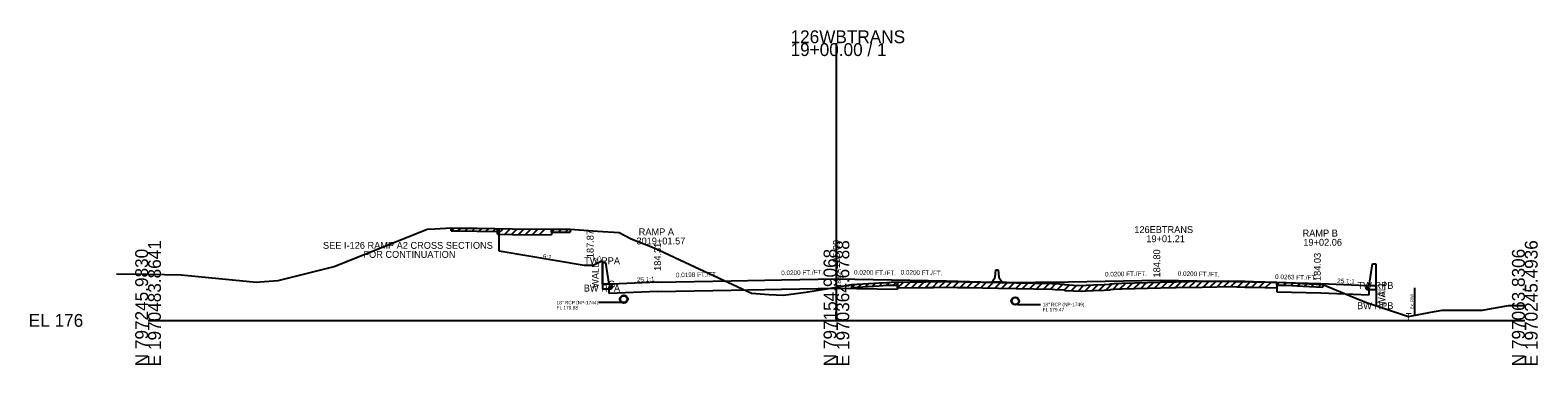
# Model space of a CAD drawing. Extents: x -6494 to 1970605, y -10 to 798140.
# Drawn here: x 974.3 to 1302.8, y 1490.3 to 1563.3 of the extents above; entities that cross this region are included whole.
import ezdxf

# ---------------------------------------------------------------- set-up
doc = ezdxf.new("R2010")
doc.units = 0
for name, color, linetype in [('Default', 7, 'Continuous'), ('RD_EX_SU_Misc_TxCode', 7, 'Continuous'), ('RD_GPK_XS_Cell', 7, 'Continuous'), ('RD_Sketch1', 7, 'Continuous'), ('RD_XS_Base', 7, 'Continuous'), ('RD_XS_Box', 7, 'Continuous'), ('RD_XS_EwShp', 7, 'Continuous'), ('RD_XS_ExGround', 7, 'Continuous'), ('RD_XS_ExPaveRet', 7, 'Continuous'), ('RD_XS_ExRW', 7, 'Continuous'), ('RD_XS_MedBWall', 7, 'Continuous'), ('RD_XS_Misc_Line', 7, 'Continuous'), ('RD_XS_Pave', 7, 'Continuous'), ('RD_XS_PaveOvlay', 7, 'Continuous'), ('RD_XS_PaveShd', 7, 'Continuous'), ('RD_XS_Pipe', 7, 'Continuous'), ('RD_XS_TieSlope', 7, 'Continuous'), ('RD_XS_TX_Elev_EX', 7, 'Continuous'), ('RD_XS_TX_Elev_PR', 7, 'Continuous'), ('RD_XS_TX_Misc', 7, 'Continuous'), ('RD_XS_TX_Notes', 7, 'Continuous'), ('RD_XS_TX_Profile', 7, 'Continuous'), ('RD_XS_TX_Slope', 7, 'Continuous'), ('RD_XS_TX_Station', 7, 'Continuous')]:
    doc.layers.add(name, color=color, linetype=linetype)

msp = doc.modelspace()

# ---------------------------------------------------------------- linework, layer by layer
at = {"layer": 'Default'}
for p, q in [((1184, 1508.57), (1184.58, 1509.41)), ((1184, 1508.32), (1184, 1508.57)), ((1186, 1508.32), (1184, 1508.32)), ((1184.58, 1509.41), (1184.75, 1510.99)), ((1184.75, 1510.99), (1185.25, 1510.99)), ((1185.25, 1510.99), (1185.42, 1509.41)), ((1185.42, 1509.41), (1186, 1508.57)), ((1186, 1508.57), (1186, 1508.32))]:
    msp.add_line(p, q, dxfattribs=at)
at = {"layer": 'RD_GPK_XS_Cell'}
for p, q in [((1150, 1500), (1150, 1560.44)), ((1000, 1500), (1150, 1500)), ((1150, 1500), (1300, 1500))]:
    msp.add_line(p, q, dxfattribs=at)
at = {"layer": 'RD_XS_Base'}
for p, q in [((1100.51, 1507.33), (1101.01, 1507.35)), ((1100.51, 1505.85), (1100.51, 1507.33)), ((1111.03, 1506.27), (1100.51, 1505.85)), ((1101.01, 1507.35), (1101.01, 1507.91)), ((1111.03, 1506.27), (1127.07, 1506.59)), ((1127.07, 1506.59), (1138, 1506.81)), ((1138, 1506.81), (1150, 1507.05)), ((1150, 1507.05), (1163.33, 1506.79)), ((1245.97, 1506.23), (1255.54, 1505.99)), ((1255.54, 1505.99), (1266.08, 1505.57)), ((1265.57, 1507.07), (1265.57, 1507.63)), ((1266.08, 1507.05), (1265.57, 1507.07)), ((1266.08, 1505.57), (1266.08, 1507.05))]:
    msp.add_line(p, q, dxfattribs=at)
at = {"layer": 'RD_XS_Box'}
for p, q in [((1099.01, 1507.91), (1099.01, 1513)), ((1101.01, 1507.91), (1099.01, 1507.91)), ((1265.57, 1507.63), (1267.58, 1507.63)), ((1267.58, 1507.63), (1267.58, 1503.2))]:
    msp.add_line(p, q, dxfattribs=at)
at = {"layer": 'RD_XS_ExGround'}
msp.add_line((993.14, 1510.18), (1000, 1510.06), dxfattribs=at)
msp.add_lwpolyline([(1000, 1510.06), (1007.24, 1509.94), (1023.66, 1508.34), (1024.35, 1508.39), (1028.35, 1508.71), (1040.54, 1511.76), (1060.83, 1519.88), (1062.47, 1519.98), (1066.06, 1520.15), (1067.38, 1520.13), (1071.68, 1520.09), (1079.4, 1519.97), (1088.65, 1519.87), (1090.68, 1519.87), (1091.95, 1519.86), (1097.92, 1519.45), (1102.65, 1519.13), (1105.27, 1517.78), (1110.26, 1515.85), (1119.17, 1511.67), (1131.47, 1505.95), (1135.25, 1505.67), (1138.44, 1505.47), (1142.27, 1506), (1143.81, 1506.26), (1150, 1507.27), (1153.33, 1507.82), (1159.29, 1508.19), (1160.96, 1508.3), (1161.92, 1508.31), (1169.5, 1508.43), (1171.12, 1508.46), (1173.49, 1508.51), (1176.35, 1508.45), (1178.24, 1508.42), (1185.34, 1508.3), (1196.94, 1508.05), (1197.69, 1508.02), (1199.55, 1507.92), (1199.77, 1507.8), (1201.65, 1507.7), (1203.34, 1507.62), (1204.4, 1507.68), (1206.01, 1507.78), (1208.31, 1507.85), (1209.51, 1507.89), (1209.71, 1507.99), (1210.53, 1508.03), (1212.17, 1508.12), (1220.62, 1508.34), (1223.58, 1508.41), (1224.01, 1508.42), (1229.68, 1508.53), (1232.89, 1508.59), (1235.52, 1508.62), (1239, 1508.53), (1239.95, 1508.5), (1240.86, 1508.47), (1248.02, 1508.27), (1251.62, 1508.08), (1255.97, 1507.85), (1264.04, 1504.52), (1265.7, 1503.84), (1266.58, 1503.54), (1274.63, 1500.84), (1279.53, 1501.79), (1281.98, 1502.24), (1287.01, 1502.25), (1290.76, 1502.24), (1291.15, 1502.32), (1296.43, 1503.22), (1298.92, 1503.22), (1300, 1503.22)], dxfattribs=at)
at = {"layer": 'RD_XS_ExPaveRet'}
for p, q in [((1066.06, 1519.52), (1066.06, 1520.15)), ((1066.06, 1519.52), (1067.38, 1519.5)), ((1067.38, 1519.5), (1071.68, 1519.46)), ((1071.68, 1519.46), (1076.15, 1519.4)), ((1076.15, 1518.77), (1076.15, 1520.02)), ((1076.15, 1520.02), (1076.15, 1519.4)), ((1076.15, 1518.77), (1079.4, 1518.72)), ((1079.4, 1518.72), (1087.92, 1518.63)), ((1087.92, 1519.88), (1087.92, 1518.63)), ((1087.92, 1519.25), (1087.92, 1519.88)), ((1087.92, 1519.25), (1088.65, 1519.24)), ((1088.65, 1519.24), (1090.68, 1519.24)), ((1090.68, 1519.24), (1091.95, 1519.24)), ((1091.95, 1519.86), (1091.95, 1519.24)), ((1163.33, 1507.08), (1163.33, 1508.33)), ((1163.33, 1508.33), (1163.33, 1507.71)), ((1245.97, 1508.33), (1245.97, 1507.08)), ((1245.97, 1507.71), (1245.97, 1508.33)), ((1153.33, 1507.19), (1153.33, 1507.82)), ((1153.33, 1507.19), (1159.29, 1507.57)), ((1159.29, 1507.57), (1160.96, 1507.67)), ((1160.96, 1507.67), (1161.92, 1507.68)), ((1161.92, 1507.68), (1163.33, 1507.71)), ((1163.33, 1507.08), (1169.5, 1507.18)), ((1169.5, 1507.18), (1171.12, 1507.21)), ((1171.12, 1507.21), (1173.49, 1507.26)), ((1173.49, 1507.26), (1176.35, 1507.2)), ((1176.35, 1507.2), (1178.24, 1507.17)), ((1178.24, 1507.17), (1185.34, 1507.05)), ((1185.34, 1507.05), (1196.94, 1506.8)), ((1196.94, 1506.8), (1197.69, 1506.77)), ((1197.69, 1506.77), (1199.55, 1506.67)), ((1199.55, 1506.67), (1199.77, 1506.55)), ((1199.77, 1506.55), (1201.65, 1506.45)), ((1201.65, 1506.45), (1203.34, 1506.37)), ((1203.34, 1506.37), (1204.4, 1506.43)), ((1204.4, 1506.43), (1206.01, 1506.53)), ((1206.01, 1506.53), (1208.31, 1506.6)), ((1208.31, 1506.6), (1209.51, 1506.64)), ((1209.51, 1506.64), (1209.71, 1506.74)), ((1209.71, 1506.74), (1210.53, 1506.78)), ((1210.53, 1506.78), (1212.17, 1506.87)), ((1212.17, 1506.87), (1220.62, 1507.09)), ((1220.62, 1507.09), (1223.58, 1507.16)), ((1223.58, 1507.16), (1224.01, 1507.17)), ((1224.01, 1507.17), (1229.68, 1507.28)), ((1229.68, 1507.28), (1232.89, 1507.34)), ((1232.89, 1507.34), (1235.52, 1507.37)), ((1235.52, 1507.37), (1239, 1507.28)), ((1239, 1507.28), (1239.95, 1507.25)), ((1239.95, 1507.25), (1240.86, 1507.22)), ((1240.86, 1507.22), (1245.97, 1507.08)), ((1245.97, 1507.71), (1248.02, 1507.65)), ((1248.02, 1507.65), (1251.62, 1507.46)), ((1251.62, 1507.46), (1255.97, 1507.23)), ((1255.97, 1507.85), (1255.97, 1507.23))]:
    msp.add_line(p, q, dxfattribs=at)
at = {"layer": 'RD_XS_ExRW'}
msp.add_line((1275.98, 1507.1), (1275.98, 1501.1), dxfattribs=at)
at = {"layer": 'RD_XS_MedBWall'}
for p, q in [((1099.76, 1512.58), (1099.01, 1512.58)), ((1099.01, 1512.58), (1099.01, 1506.91)), ((1100.51, 1507.91), (1099.76, 1512.58)), ((1266.07, 1507.63), (1266.82, 1512.3)), ((1266.82, 1512.3), (1267.57, 1512.3)), ((1267.57, 1512.3), (1267.57, 1506.63)), ((1099.01, 1506.91), (1101.01, 1506.91)), ((1101.01, 1507.91), (1100.51, 1507.91)), ((1101.01, 1506.91), (1101.01, 1507.91)), ((1265.57, 1506.63), (1265.57, 1507.63)), ((1265.57, 1507.63), (1266.07, 1507.63)), ((1267.57, 1506.63), (1265.57, 1506.63))]:
    msp.add_line(p, q, dxfattribs=at)
at = {"layer": 'RD_XS_Misc_Line'}
for p, q in [((1066.06, 1519.52), (1066.68, 1520.14)), ((1067.57, 1519.5), (1068.2, 1520.12)), ((1069.09, 1519.49), (1069.71, 1520.11)), ((1070.6, 1519.47), (1071.22, 1520.09)), ((1072.11, 1519.45), (1072.73, 1520.07)), ((1073.63, 1519.43), (1074.25, 1520.05)), ((1075.14, 1519.41), (1075.76, 1520.03)), ((1076.15, 1518.77), (1077.39, 1520)), ((1077.66, 1518.75), (1078.9, 1519.98)), ((1079.17, 1518.73), (1080.42, 1519.96)), ((1080.69, 1518.71), (1081.93, 1519.95)), ((1082.2, 1518.69), (1083.45, 1519.93)), ((1083.71, 1518.67), (1084.96, 1519.91)), ((1085.23, 1518.66), (1086.47, 1519.89)), ((1087.92, 1519.25), (1088.54, 1519.87)), ((1089.43, 1519.24), (1090.06, 1519.87)), ((1090.94, 1519.24), (1091.57, 1519.86)), ((1156.36, 1507.38), (1157.03, 1508.05)), ((1157.87, 1507.48), (1158.54, 1508.14)), ((1159.38, 1507.57), (1160.06, 1508.24)), ((1160.9, 1507.67), (1161.54, 1508.3)), ((1162.41, 1507.69), (1163.05, 1508.33)), ((1163.33, 1507.08), (1164.61, 1508.35)), ((1164.84, 1507.11), (1166.13, 1508.38)), ((1166.36, 1507.13), (1167.64, 1508.4)), ((1167.87, 1507.16), (1169.15, 1508.43)), ((1169.38, 1507.18), (1170.67, 1508.46)), ((1170.9, 1507.21), (1172.18, 1508.48)), ((1172.41, 1507.24), (1173.69, 1508.5)), ((1173.92, 1507.25), (1175.16, 1508.48)), ((1175.44, 1507.22), (1176.68, 1508.45)), ((1176.95, 1507.19), (1178.19, 1508.42)), ((1178.46, 1507.17), (1179.7, 1508.4)), ((1179.98, 1507.14), (1181.22, 1508.37)), ((1181.49, 1507.12), (1182.73, 1508.35)), ((1183, 1507.09), (1184.24, 1508.32)), ((1184.52, 1507.06), (1185.75, 1508.29)), ((1186.03, 1507.04), (1187.26, 1508.26)), ((1187.54, 1507), (1188.78, 1508.23)), ((1189.06, 1506.97), (1190.29, 1508.19)), ((1190.57, 1506.94), (1191.8, 1508.16)), ((1192.08, 1506.91), (1193.32, 1508.13)), ((1193.6, 1506.87), (1194.83, 1508.1)), ((1195.11, 1506.84), (1196.34, 1508.07)), ((1196.62, 1506.81), (1197.83, 1508.01)), ((1208.73, 1506.62), (1210.14, 1508.01)), ((1210.24, 1506.77), (1211.57, 1508.09)), ((1211.76, 1506.85), (1213.06, 1508.14)), ((1213.27, 1506.9), (1214.56, 1508.18)), ((1214.78, 1506.94), (1216.08, 1508.22)), ((1216.3, 1506.98), (1217.59, 1508.26)), ((1217.81, 1507.02), (1219.1, 1508.3)), ((1219.32, 1507.05), (1220.62, 1508.34)), ((1220.83, 1507.09), (1222.13, 1508.38)), ((1222.35, 1507.13), (1223.64, 1508.42)), ((1223.86, 1507.17), (1225.15, 1508.44)), ((1225.37, 1507.2), (1226.66, 1508.47)), ((1226.89, 1507.23), (1228.17, 1508.5)), ((1228.4, 1507.25), (1229.69, 1508.53)), ((1229.91, 1507.28), (1231.2, 1508.56)), ((1231.43, 1507.31), (1232.71, 1508.58)), ((1232.94, 1507.34), (1234.22, 1508.6)), ((1234.45, 1507.36), (1235.72, 1508.62)), ((1235.97, 1507.36), (1237.19, 1508.58)), ((1237.48, 1507.32), (1238.71, 1508.53)), ((1238.99, 1507.28), (1240.22, 1508.49)), ((1240.51, 1507.23), (1241.73, 1508.45)), ((1242.02, 1507.19), (1243.25, 1508.41)), ((1243.53, 1507.15), (1244.76, 1508.36)), ((1245.97, 1507.71), (1246.58, 1508.31)), ((1247.48, 1507.66), (1248.09, 1508.27)), ((1248.99, 1507.6), (1249.59, 1508.19)), ((1250.51, 1507.52), (1251.1, 1508.11)), ((1252.02, 1507.44), (1252.62, 1508.03)), ((1153.33, 1507.19), (1154, 1507.86)), ((1154.84, 1507.29), (1155.52, 1507.95)), ((1198.14, 1506.74), (1199.33, 1507.93)), ((1199.65, 1506.62), (1200.79, 1507.75)), ((1201.16, 1506.48), (1202.36, 1507.66)), ((1202.68, 1506.4), (1203.94, 1507.65)), ((1204.19, 1506.42), (1205.53, 1507.75)), ((1205.7, 1506.51), (1207.02, 1507.81)), ((1207.22, 1506.57), (1208.52, 1507.86)), ((1253.53, 1507.36), (1254.13, 1507.95)), ((1255.05, 1507.27), (1255.64, 1507.87))]:
    msp.add_line(p, q, dxfattribs=at)
at = {"layer": 'RD_XS_Pave'}
for p, q in [((1111.03, 1508.31), (1127.07, 1508.63)), ((1138, 1508.85), (1150, 1509.09)), ((1150, 1509.09), (1174, 1508.61)), ((1196.55, 1508.32), (1220.55, 1508.8)), ((1220.55, 1508.8), (1232.55, 1508.56)), ((1232.55, 1508.56), (1244.55, 1508.32)), ((1244.55, 1508.32), (1255.54, 1508.03))]:
    msp.add_line(p, q, dxfattribs=at)
at = {"layer": 'RD_XS_PaveOvlay'}
for p, q in [((1163.33, 1508.33), (1169.5, 1508.43)), ((1163.33, 1508.33), (1163.33, 1506.79)), ((1169.5, 1508.43), (1171.12, 1508.46)), ((1171.12, 1508.46), (1173.49, 1508.51)), ((1173.49, 1508.51), (1176.35, 1508.45)), ((1176.35, 1508.45), (1178.24, 1508.42)), ((1178.24, 1508.42), (1185.34, 1508.3)), ((1185.34, 1508.3), (1196.94, 1508.05)), ((1196.94, 1508.05), (1197.69, 1508.02)), ((1197.69, 1508.02), (1199.55, 1507.92)), ((1209.51, 1507.89), (1209.71, 1507.99)), ((1209.71, 1507.99), (1210.53, 1508.03)), ((1210.53, 1508.03), (1212.17, 1508.12)), ((1212.17, 1508.12), (1220.62, 1508.34)), ((1220.62, 1508.34), (1223.58, 1508.41)), ((1223.58, 1508.41), (1224.01, 1508.42)), ((1224.01, 1508.42), (1229.68, 1508.53)), ((1229.68, 1508.53), (1232.89, 1508.59)), ((1232.89, 1508.59), (1235.52, 1508.62)), ((1235.52, 1508.62), (1239, 1508.53)), ((1239, 1508.53), (1239.95, 1508.5)), ((1239.95, 1508.5), (1240.86, 1508.47)), ((1240.86, 1508.47), (1245.97, 1508.33)), ((1245.97, 1508.33), (1245.97, 1506.23)), ((1199.55, 1507.92), (1199.77, 1507.8)), ((1199.77, 1507.8), (1201.65, 1507.7)), ((1201.65, 1507.7), (1203.34, 1507.62)), ((1203.34, 1507.62), (1204.4, 1507.68)), ((1204.4, 1507.68), (1206.01, 1507.78)), ((1206.01, 1507.78), (1208.31, 1507.85)), ((1208.31, 1507.85), (1209.51, 1507.89))]:
    msp.add_line(p, q, dxfattribs=at)
at = {"layer": 'RD_XS_PaveShd'}
for p, q in [((1111.03, 1508.31), (1101.01, 1507.91)), ((1127.07, 1508.63), (1138, 1508.85)), ((1174, 1508.61), (1184, 1508.32)), ((1190.21, 1508.2), (1184, 1508.32)), ((1196.55, 1508.32), (1190.21, 1508.2)), ((1255.54, 1508.03), (1265.57, 1507.63))]:
    msp.add_line(p, q, dxfattribs=at)
at = {"layer": 'RD_XS_Pipe'}
for p, q in [((1103.16, 1503.88), (1098.16, 1503.88)), ((1189.46, 1503.47), (1194.46, 1503.47))]:
    msp.add_line(p, q, dxfattribs=at)
for centre, radius in [((1103.66, 1504.63), 0.85), ((1103.66, 1504.63), 0.75), ((1188.96, 1504.22), 0.85), ((1188.96, 1504.22), 0.75)]:
    msp.add_circle(centre, radius, dxfattribs=at)
at = {"layer": 'RD_XS_TieSlope'}
for p, q in [((1076.52, 1515.08), (1076.52, 1520.02)), ((1095.01, 1512), (1076.52, 1515.08)), ((1097.01, 1512), (1095.01, 1512)), ((1099.01, 1513), (1097.01, 1512))]:
    msp.add_line(p, q, dxfattribs=at)

# ---------------------------------------------------------------- texts
at = {"layer": 'RD_EX_SU_Misc_TxCode'}
msp.add_text('G', height=1.5, dxfattribs=at).set_placement((1100.26, 1507.16))
at = {"layer": 'RD_GPK_XS_Cell'}
for s, p in [('126WBTRANS', (1140, 1560.44)), ('19+00.00 / 1', (1140, 1557.64)), ('EL 176', (974, 1498.6))]:
    msp.add_text(s, height=2.8, dxfattribs=at).set_placement(p)
for s, p in [('N 797245.9830', (1000, 1490)), ('E 1970483.8641', (1002.8, 1490)), ('N 797154.9068', (1150, 1490)), ('E 1970364.6788', (1152.8, 1490)), ('N 797063.8306', (1300, 1490)), ('E 1970245.4936', (1302.8, 1490))]:
    msp.add_text(s, height=2.8, rotation=90, dxfattribs=at).set_placement(p)
at = {"layer": 'RD_Sketch1'}
msp.add_text('T', height=1.5, dxfattribs=at).set_placement((1274.08, 1500.09))
at = {"layer": 'RD_XS_EwShp'}
for s, p in [('TW RPA', (1095.04, 1512.25)), ('TW RPB', (1263.56, 1506.88)), ('BW RPA', (1094.94, 1506.29)), ('BW RPB', (1263.45, 1502.45))]:
    msp.add_text(s, height=1.5, dxfattribs=at).set_placement(p)
at = {"layer": 'RD_XS_ExRW'}
msp.add_text('Ex. R/W ', height=0.65, rotation=90, dxfattribs=at).set_placement((1275.73, 1502.48))
at = {"layer": 'RD_XS_Pipe'}
for s, p in [('18" RCP (NP-1744)', (1089.01, 1503.51)), ('FL 179.88', (1089.01, 1502.38)), ('18" RCP (NP-1749)', (1194.96, 1503.09)), ('FL 179.47', (1194.96, 1501.97))]:
    msp.add_text(s, height=0.75, dxfattribs=at).set_placement(p)
at = {"layer": 'RD_XS_TX_Elev_EX'}
msp.add_text('183.27', height=1, rotation=90, dxfattribs=at).set_placement((1151, 1507.27))
at = {"layer": 'RD_XS_TX_Elev_PR'}
for s, p in [('184.31', (1111.78, 1510.79)), ('185.09', (1150.75, 1511.42)), (' 184.80', (1220.55, 1508.8)), (' 184.03', (1255.54, 1508.03))]:
    msp.add_text(s, height=1.5, rotation=90, dxfattribs=at).set_placement(p)
at = {"layer": 'RD_XS_TX_Misc'}
msp.add_text('187.87', height=1.5, rotation=90, dxfattribs=at).set_placement((1097.09, 1513.57))
at = {"layer": 'RD_XS_TX_Notes'}
for s, p in [('SEE I-126 RAMP A2 CROSS SECTIONS', (1038.12, 1515.61)), ('FOR CONTINUATION', (1046.93, 1513.64))]:
    msp.add_text(s, height=1.5, dxfattribs=at).set_placement(p)
for p in [(1098.2, 1507.1), (1269.58, 1503.15)]:
    msp.add_text('WALL', height=1.5, rotation=90, dxfattribs=at).set_placement(p)
at = {"layer": 'RD_XS_TX_Profile'}
msp.add_text('25.1:1', height=1, rotation=357.7169, dxfattribs=at).set_placement((1259.09, 1508.14))
at = {"layer": 'RD_XS_TX_Slope'}
for s, rotation, p in [('6:1', 350.5377, (1085.96, 1513.5)), ('2:1', 26.5651, (1097.41, 1512.51)), ('25.1:1', 2.2855, (1106.53, 1508.38)), ('0.0198 FT./FT.', 1.1368, (1115.03, 1509.39)), ('0.0200 FT./FT.', 1.1458, (1137.98, 1509.85)), ('0.0200 FT./FT.', 358.8542, (1153.83, 1510.02)), ('0.0200 FT./FT.', 358.8542, (1163.98, 1510)), ('0.0200 FT./FT.', 1.1455, (1208.53, 1509.56)), ('0.0200 FT./FT.', 358.854, (1224.37, 1509.73)), ('0.0263 FT./FT.', 358.4953, (1245.58, 1509.04)), ('4:1', 345.9639, (1267.74, 1505.48))]:
    msp.add_text(s, height=1, rotation=rotation, dxfattribs=at).set_placement(p)
at = {"layer": 'RD_XS_TX_Station'}
for s, p in [('3019+01.57', (1106.42, 1516.56)), ('RAMP A', (1106.92, 1518.56)), ('126EBTRANS', (1214.9, 1519.05)), ('19+01.21', (1217.52, 1517.05)), ('RAMP B', (1251.57, 1518.28)), ('19+02.06', (1251.74, 1516.28))]:
    msp.add_text(s, height=1.5, dxfattribs=at).set_placement(p)

doc.saveas('drawing.dxf')
